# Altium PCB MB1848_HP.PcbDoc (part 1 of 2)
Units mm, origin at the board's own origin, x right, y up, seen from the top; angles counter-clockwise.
Board outline 61.5 x 34 mm, 4 copper layers (Top Layer, MidLayer 1, MidLayer 2, Bottom Layer), stack 1.035 mm thick; 124 components, 86 nets, 341 pads, 1082 vias.
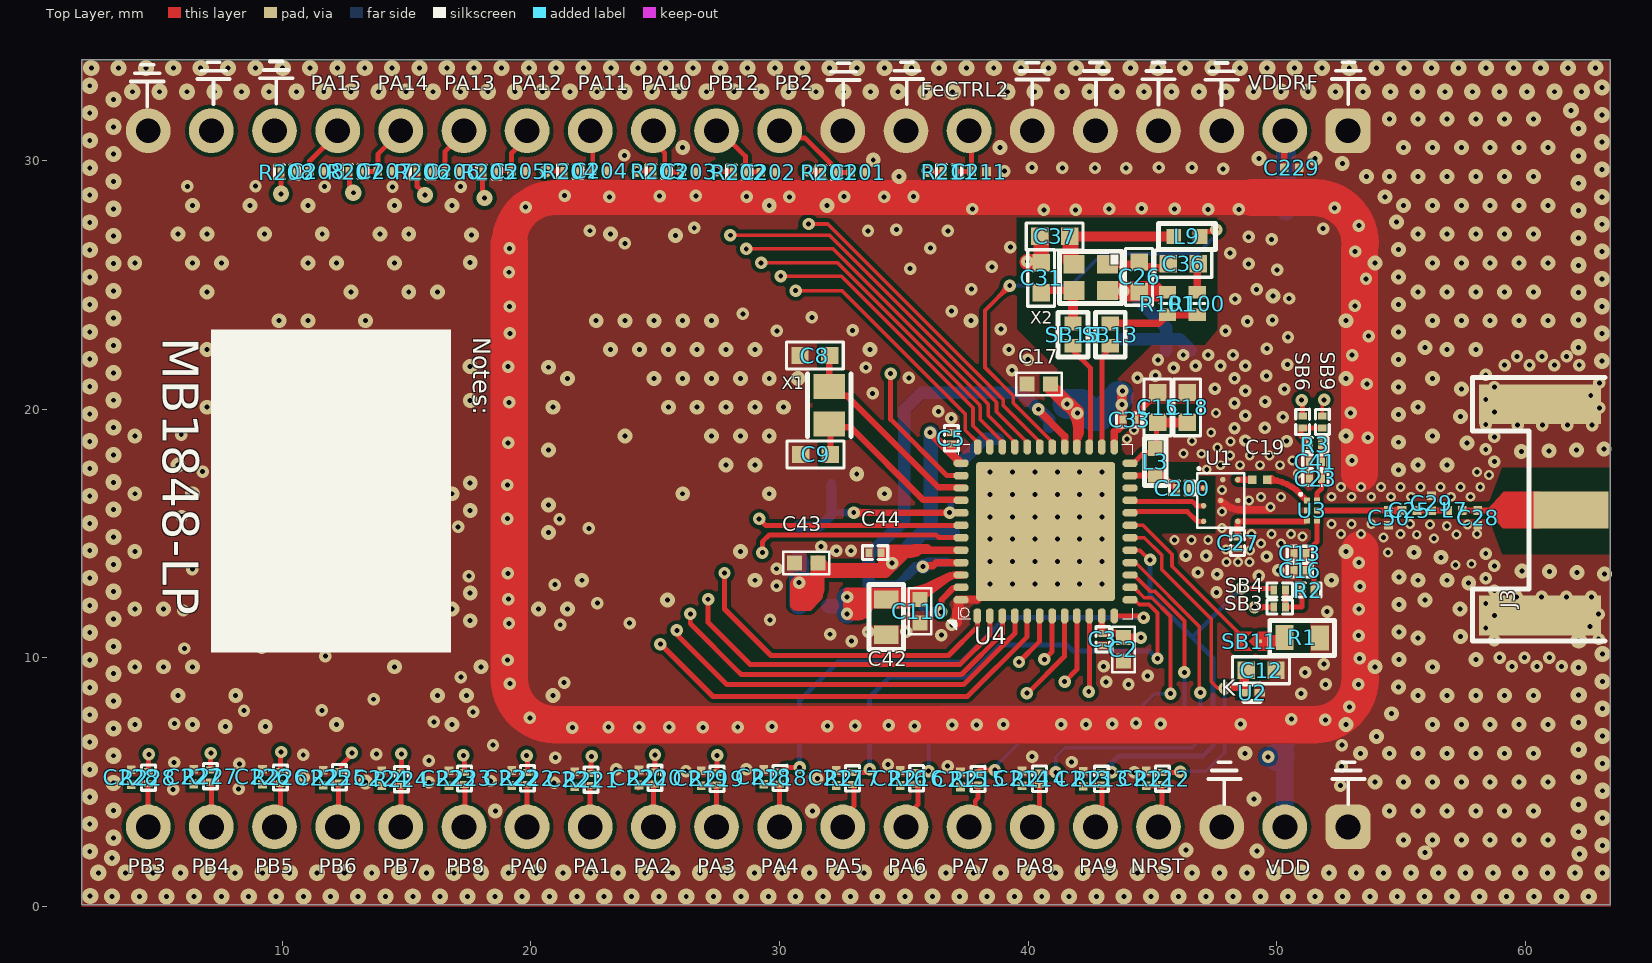
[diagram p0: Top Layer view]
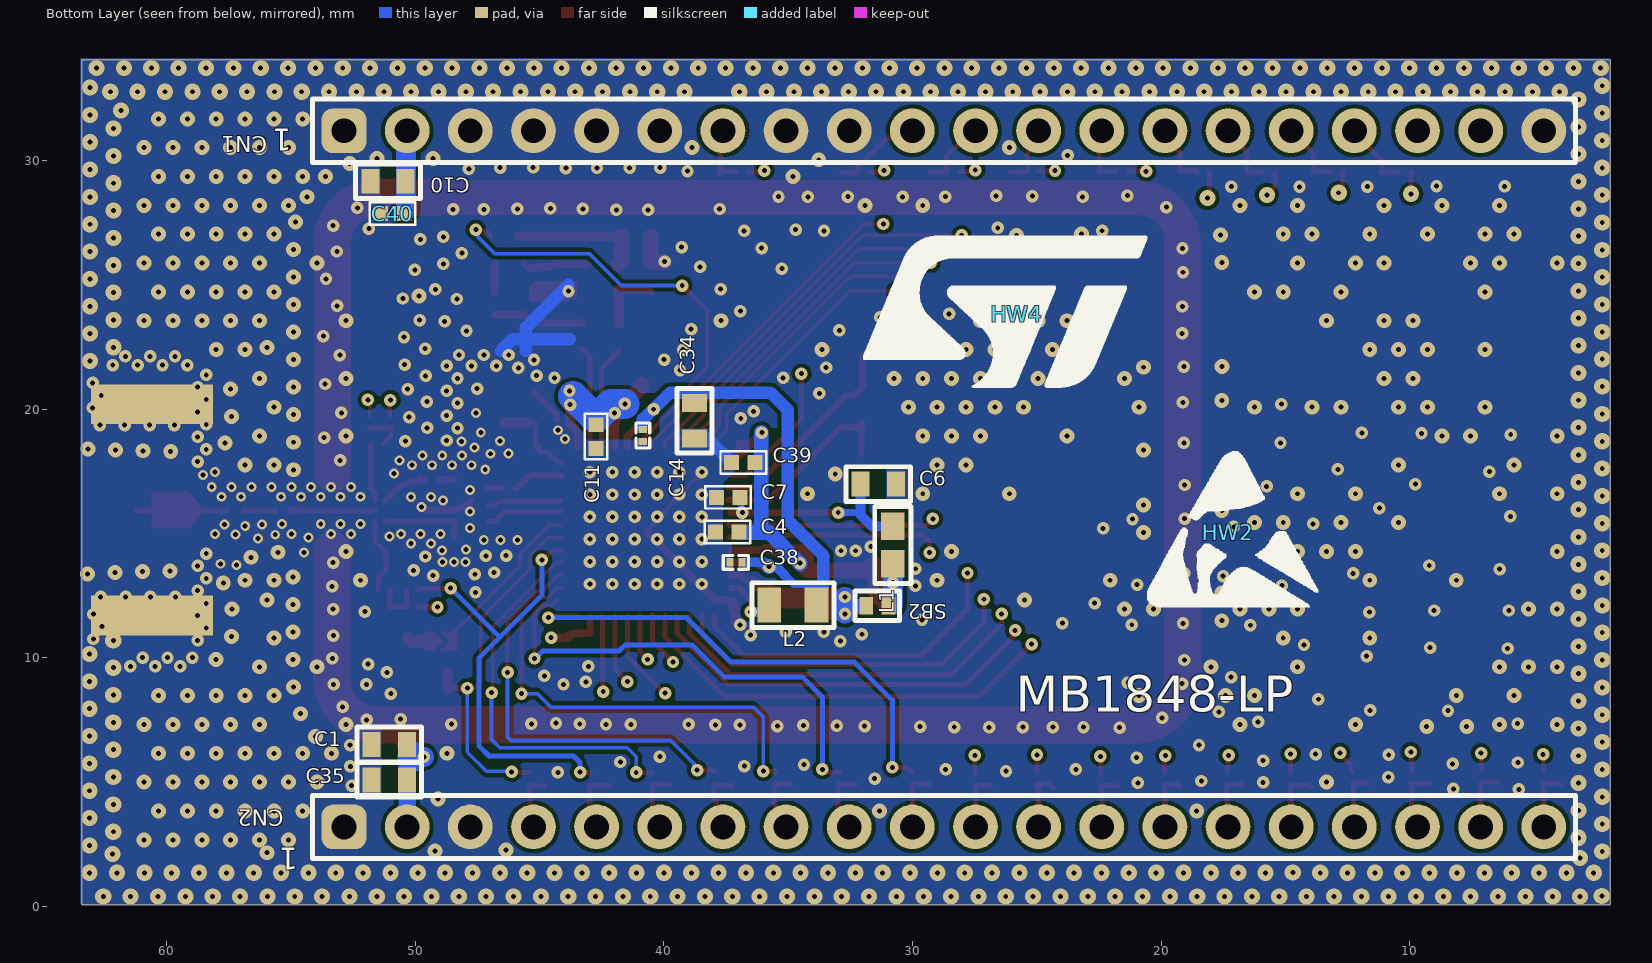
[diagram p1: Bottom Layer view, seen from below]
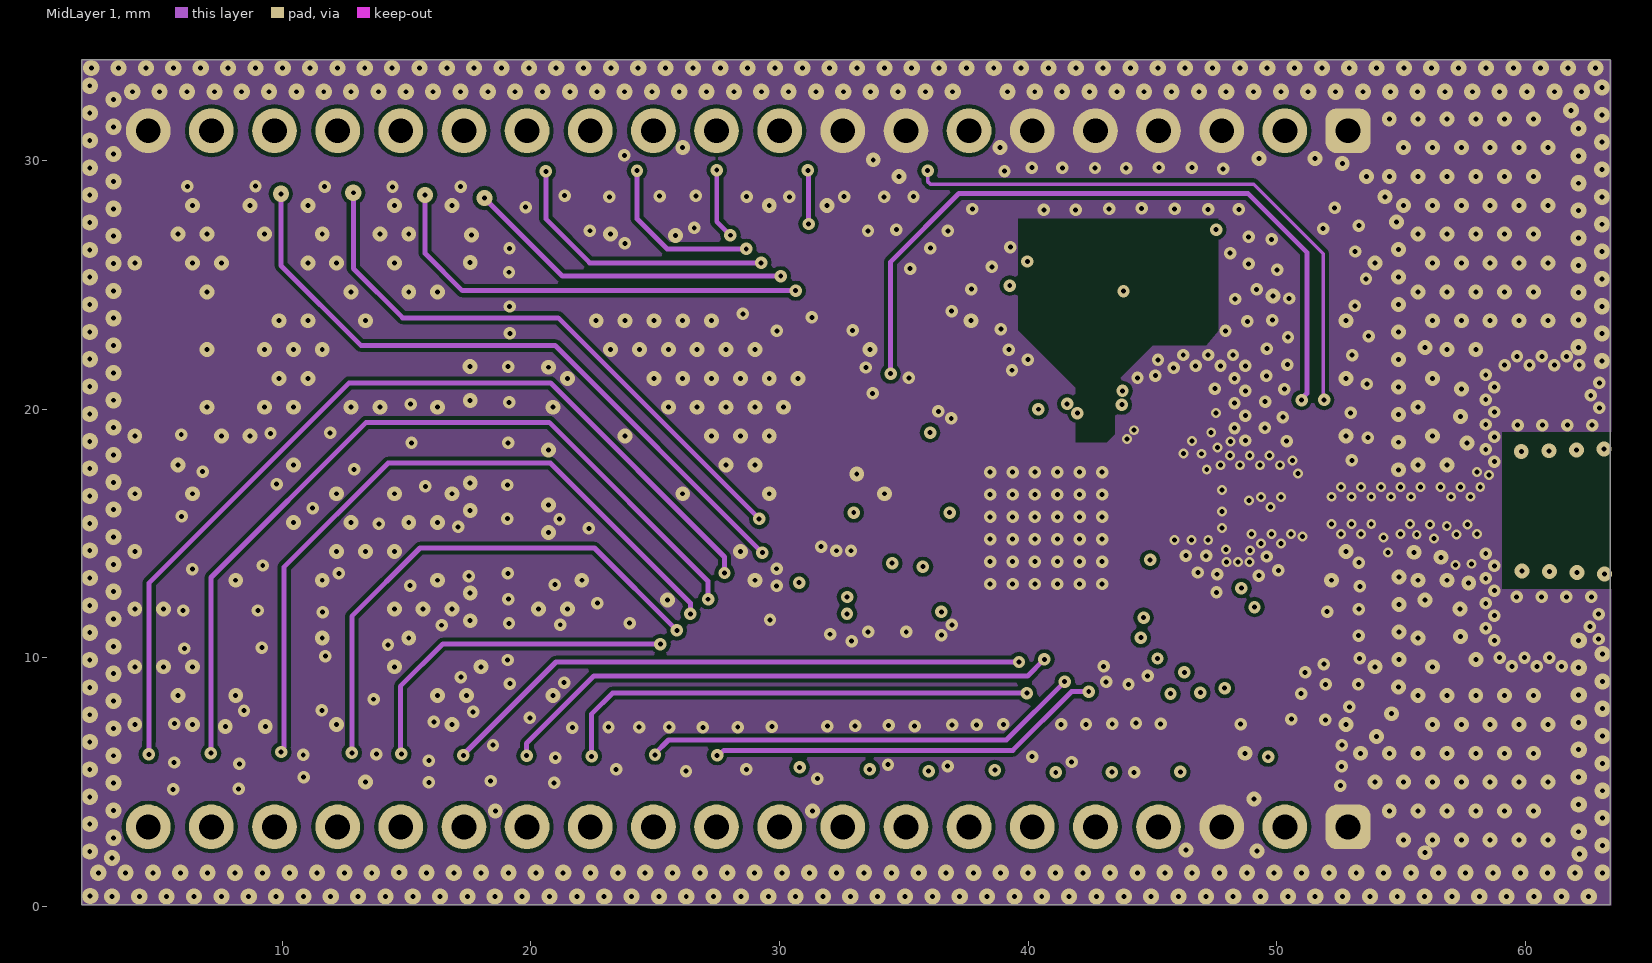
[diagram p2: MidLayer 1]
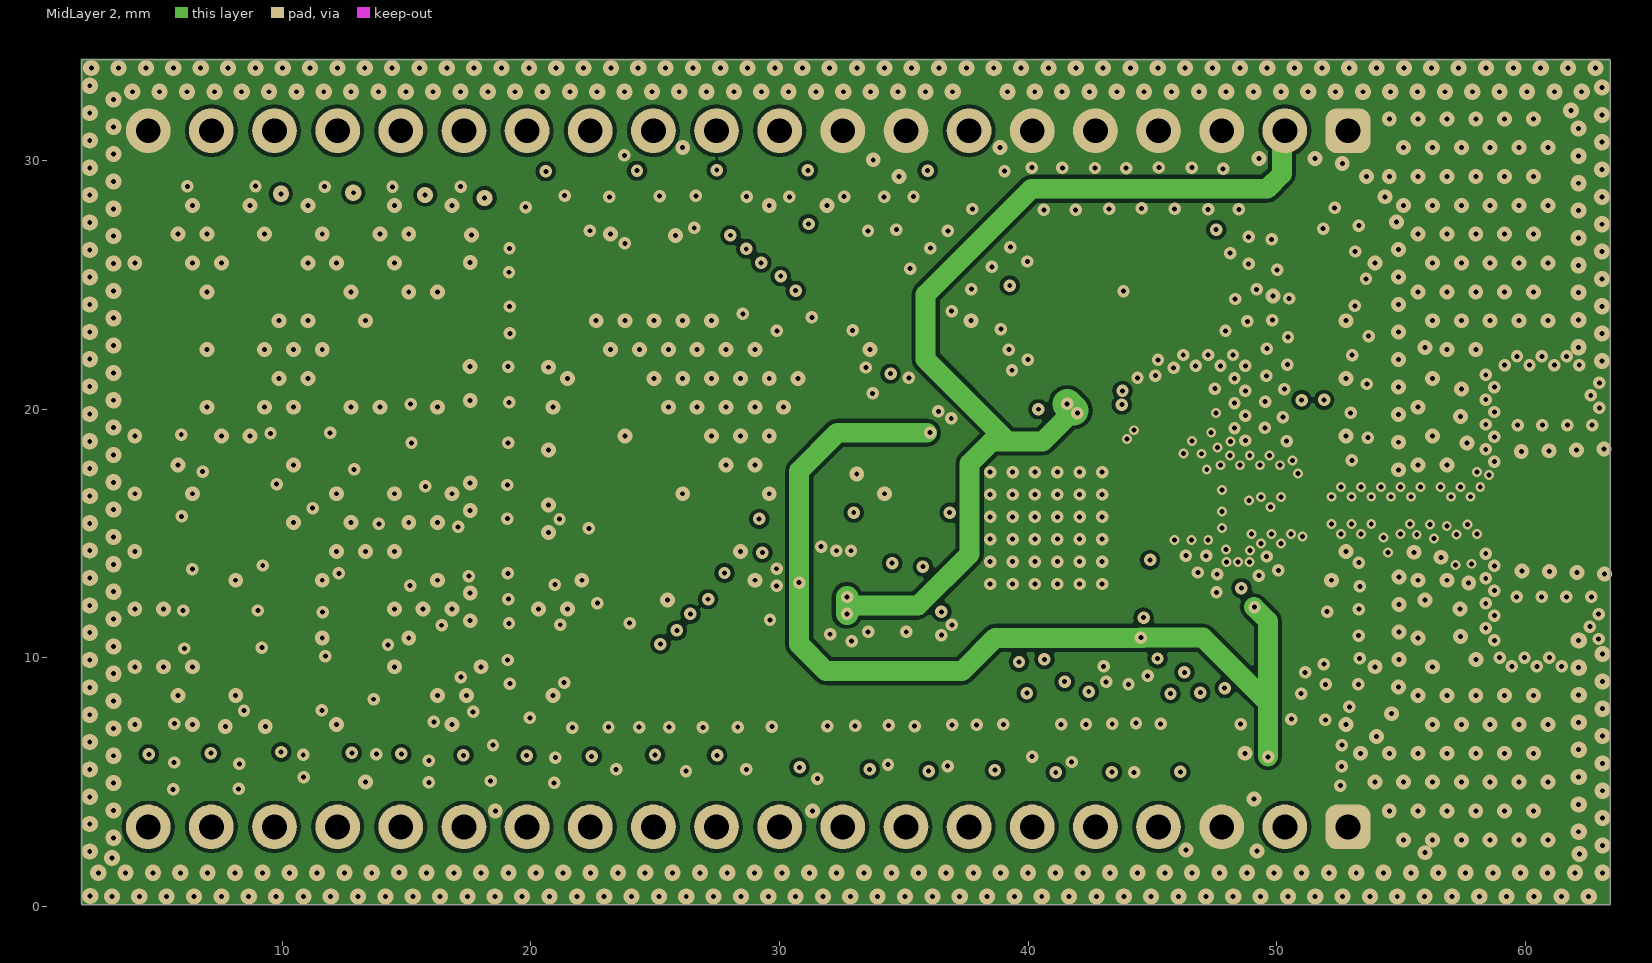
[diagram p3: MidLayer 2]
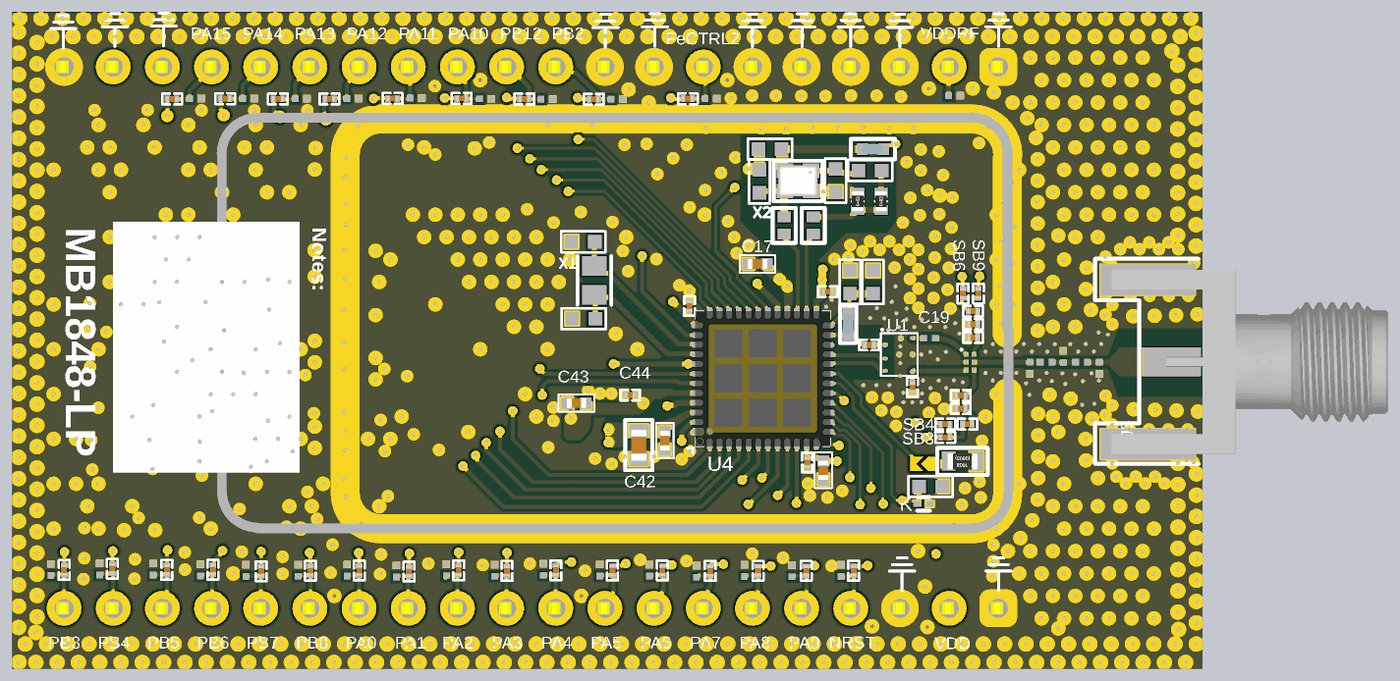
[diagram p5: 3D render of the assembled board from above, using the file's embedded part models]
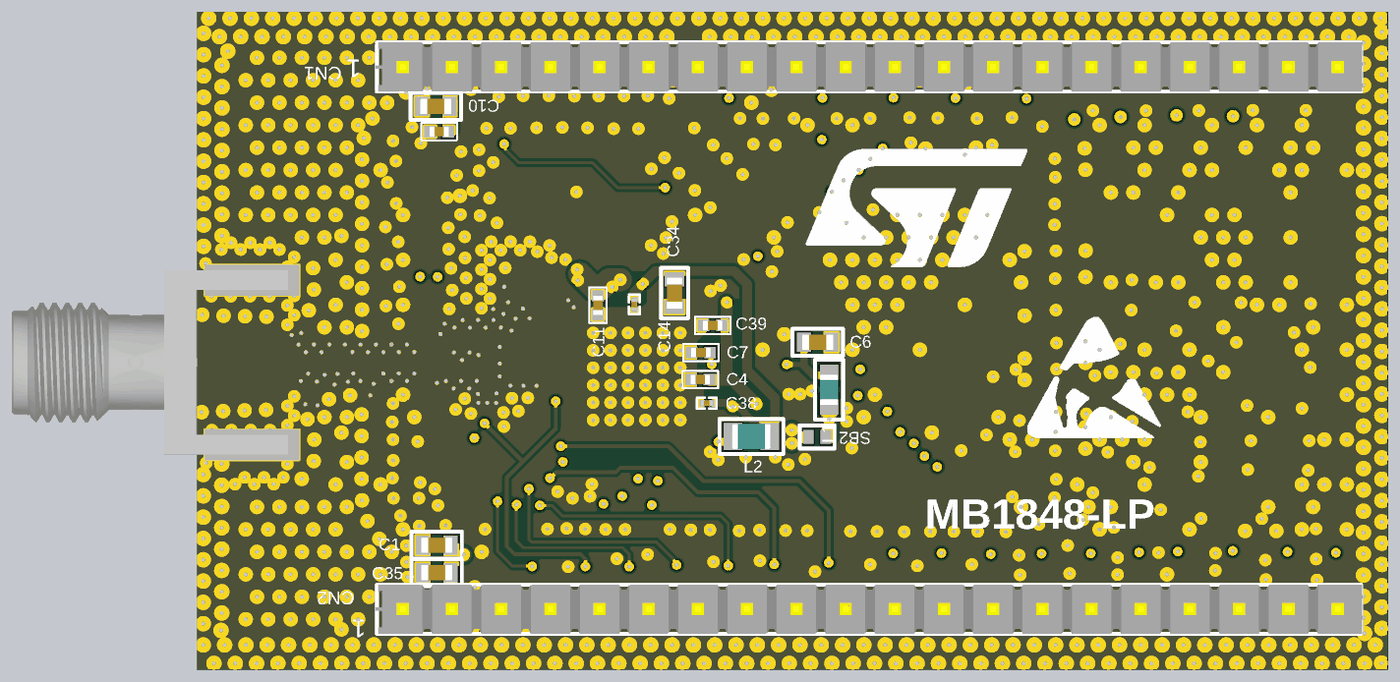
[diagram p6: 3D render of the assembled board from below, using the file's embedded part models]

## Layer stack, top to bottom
Top Solder: solder mask 0.01, Solder Resist, Dk 3.5
Top Layer: signal copper 0.035
Dielectric 2: prepreg 0.16, 1 x 2116 + 1 x 106, Dk 3.7
MidLayer 1: signal copper 0.0175
Dielectric 1: core 0.61, FR-4, Dk 5
MidLayer 2: signal copper 0.0175
Dielectric 3: prepreg 0.16, 1 x 2116 + 1 x 106, Dk 3.7
Bottom Layer: signal copper 0.035
Bottom Solder: solder mask 0.01, Solder Resist, Dk 3.5

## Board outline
1.922,0.056 63.42,0.056 63.42,34.056 1.942,34.056 1.922,34.056

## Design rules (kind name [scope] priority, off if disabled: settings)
BoardOutlineClearance [All] p1 off: gap=0.6 ignorepadtopadclearanceinfootprint=FALSE
Clearance Clearance_GND_50ohm [InNetClass('50ohm') or  (InDifferentialPairClass('All Differential Pairs')) vs InNamedPolygon('TOP_LAYER_GND')] p1: gap=0.175 ignorepadtopadclearanceinfootprint=FALSE except(0: Arc-Hole Track-Hole SMDPad-Hole THPad-Hole Via-Hole Fill-Hole Poly-Hole Region-Hole Text-Hole; 0.165: Arc-Fill Arc-Poly Arc-Region Track-Fill Track-Poly Track-Region)
Clearance Clearance_tab [(ObjectKind = 'Pad') And (Name Like 'Tab*-*') vs OnLayer('Keep-Out Layer')] p2: gap=0 ignorepadtopadclearanceinfootprint=FALSE
Clearance Clearance_via_to_via [(ObjectKind = 'Via') And (Net <> 'GND') vs (ObjectKind = 'Via') And (Net <> 'GND')] p3: gap=0.25 ignorepadtopadclearanceinfootprint=FALSE except(0: Arc-Hole Track-Hole SMDPad-Hole THPad-Hole Via-Hole Fill-Hole Poly-Hole Region-Hole Text-Hole)
Clearance [All] p4: gap=0.1 ignorepadtopadclearanceinfootprint=FALSE except(0: Arc-Hole Track-Hole SMDPad-Hole THPad-Hole Via-Hole Fill-Hole Poly-Hole Region-Hole Text-Hole; 0.15: Arc-Fill Arc-Poly Arc-Region Track-Fill Track-Poly Track-Region SMDPad-Fill SMDPad-Poly SMDPad-Region THPad-Fill THPad-Poly THPad-Region Via-Fill Via-Poly Via-Region Fill-Fill Fill-Poly Fill-Region Poly-Poly Poly-Region Region-Region)
ComponentClearance [All] p1: gap=0 collisioncheckmode=3 verticalgap=0.1 showdistances=FALSE
DiffPairsRouting [InDifferentialPair('RFI')] p1: maxlimit=0.3 minlimit=0.25 mostfreqgap=0.3 toplayer_minwidth=0.1 toplayer_maxwidth=0.24 toplayer_prefwidth=0.1 midlayer1_minwidth=0.145 midlayer1_maxwidth=0.24 midlayer1_prefwidth=0.145 midlayer2_minwidth=0.145 midlayer2_maxwidth=0.24 midlayer2_prefwidth=0.145 bottomlayer_minwidth=0.1 bottomlayer_maxwidth=0.24 bottomlayer_prefwidth=0.1 maxuncoupledlength=12.7
HoleSize [All] p1: absolutevalues=TRUE maxlimit=10 minlimit=0.025 maxpercent=80.000 minpercent=20.000
HoleToHoleClearance [All] p1: gap=0.25 allowstackedmicrovias=TRUE
MaximumViaCount MaximumViaCount_5 [InNet('GND')] p1: limit=1300
MaximumViaCount MaximumViaCount_4 [InNet('VDDRF1V55')] p2: limit=1000
MaximumViaCount MaximumViaCount_3 [InNet('VDDPA')] p3: limit=1000
MaximumViaCount MaximumViaCount_2 [InNet('VDDRF')] p4: limit=1000
MaximumViaCount MaximumViaCount_1 [InNet('VDD')] p5: limit=1000
MaximumViaCount [All] p6: limit=3
MinimumSolderMaskSliver [All] p1: minsoldermaskwidth=0.1
PlaneConnect [InNet('GND')] p1: planeconnectstyle=Relief reliefexpansion=0.508 reliefentries=4 reliefconductorwidth=0.21 reliefairgap=0.21
PolygonConnect PolygonConnect_J1 [(ObjectKind = 'Pad') And (Name = 'J1-2')] p1: connectstyle=Direct reliefconductorwidth=0.254 reliefentries=4 polygonreliefangle="90 Angle" airgapwidth=0.254
PolygonConnect PolygonConnect_All [All] p2: connectstyle=Direct reliefconductorwidth=0.25 reliefentries=4 polygonreliefangle="90 Angle" airgapwidth=0.25
RoutingLayers "RoutingLayers_90 Ohms" [InDifferentialPairClass('All Differential Pairs')] p1: top layer_v5=TRUE mid layer 1_v5=TRUE mid layer 2_v5=TRUE bottom layer_v5=TRUE
RoutingLayers [All] p2: top layer_v5=TRUE mid layer 1_v5=TRUE mid layer 2_v5=TRUE bottom layer_v5=TRUE
RoutingVias RoutingVias_BGA [InDrillLayerPair('Top Layer - MidLayer 1')] p1: holewidth=0.125 width=0.25 viastyle="Through Hole" minholewidth=0.125 minwidth=0.25 maxholewidth=0.125 maxwidth=0.3
RoutingVias [All] p2: holewidth=0.2 width=0.65 viastyle="Through Hole" minholewidth=0.2 minwidth=0.4 maxholewidth=0.2 maxwidth=0.7
ShortCircuit [(ObjectKind = 'Via') And (DrillPair = 'Top Layer - MidLayer 1') vs Ispad] p1: allowed=TRUE
SilkToSilkClearance [All] p1: silktosilkclearance=0.08
SilkToSolderMaskClearance [IsPad] p1: minsilkscreentomaskgap=0.08 clearancetoexposedcopper=TRUE
SolderMaskExpansion SolderMaskExpansion_VIA [IsVia] p1: expansion=-0.2 istentingtop=FALSE
SolderMaskExpansion [All] p2: expansion=0.075 istentingtop=FALSE
Width Width_50Ohms [InNetClass('50Ohms')] p1: maxlimit=0.7 minlimit=0.1 preferedwidth=0.24 midlayer1_maxwidth=0.5 midlayer2_maxwidth=0.5 bottomlayer_maxwidth=0.5 minimp=50.000000 maximp=50.000000 favimp=50.000000
Width [All] p2: maxlimit=2 minlimit=0.08 preferedwidth=0.15 toplayer_minwidth=0.097 toplayer_maxwidth=1.5 midlayer1_maxwidth=1 midlayer2_minwidth=0.1 bottomlayer_minwidth=0.1 bottomlayer_maxwidth=1.5 minimp=50.000000 maximp=50.000000 favimp=50.000000
20 further rules are at their usual default settings.

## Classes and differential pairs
component class Reference_Design_STM32WL_4L_IPD_ST: C1 C2 C3 C4 C5 C6 C7 C8 C9 C10 C11 C12 C13 C14 C15 C16 C17 C18 C19 C23 C25 C26 C27 C28 C29 C31 C33 C34 C35 C36 C37 C38 C39 C40 C41 C42 C43 C44 C110 CN1 CN2 J3 L1 L2 L3 L7 L9 R1 R2 R3 R100 R101 S1 SB2 SB3 SB4 SB6 SB9 SB11 SB13 SB15 U1 U2 U3 U4 X1 X2
net class 50ohm: NetC15_1 NetC19_1 NetC19_2 NetC25_1 NetC25_2 NetC27_2 NetC28_2
differential pair RFI: +RFI_P -RFI_N

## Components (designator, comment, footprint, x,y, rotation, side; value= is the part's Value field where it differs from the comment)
C1 "" CAPC1608X09N 51.049,6.501 r180 bottom
C2 "" CAPC1005X06N 43.826,10.333 r90 top
C3 "" 0201 43.003,10.492 r90 top
C4 "" CAPC1005X06N 37.443,15.048 r180 bottom
C5 "" 0201 36.91,19.063 r270 top
C6 "" CAPC1608X09N 31.375,16.977 r180 bottom
C7 "" CAPC1005X06N 37.41,16.448 r0 bottom
C8 "Capacitor" 0402 32.016,22.152 r180 top
C9 "Capacitor" 0402 32.043,18.172 r180 top
C10 "" CAPC1608X09N 51.093,29.164 r0 bottom
C11 "" CAPC1005X06N 42.723,18.892 r270 bottom
C12 "" 0402 48.768,9.492 r0 top
C13 "MCD-00198" 0201 50.687,14.2 r0 top
C14 "" CAPC1608X09N 38.769,19.522 r270 bottom
C15 "" 0402 45.203,19.467 r90 top
C16 "MCD-00102" 0201 50.687,13.515 r0 top
C17 "" CAPC1005X06N 40.427,21.003 r180 top
C18 "" 0402 46.393,20.663 r270 top
C19 "RFCapacitor_201" rlc_201_smd 49.311,17.158 r180 top
C23 "MCD-00198" 0201 51.312,17.196 r0 top
C25 "RFCapacitor_201" rlc_201_smd 55.336,15.919 r0 top
C26 "Capacitor" 0402 44.458,25.913 r270 top
C27 "NC" 0201 48.428,14.381 r90 top
C28 "RFCapacitor_201" rlc_201_smd 58.084,15.619 r90 top
C29 "RFCapacitor_201" rlc_201_smd 56.22,16.209 r270 top
C31 "Capacitor" 0402 40.521,24.68 r90 top
C33 "" 0201 44.296,19.562 r180 top
C34 "" 0201 40.843,18.693 r90 bottom
C35 "" CAPC1608X09N 51.049,5.083 r180 bottom
C36 "" 0402 46.836,25.842 r180 top
C37 "" 0402 40.468,26.942 r0 top
C38 "" 0201 36.863,13.832 r0 bottom
C39 "" CAPC1005X06N 36.802,17.848 r0 bottom
C40 "" CAPC1005X06N 50.916,27.859 r0 bottom
C41 "MCD-00102" 0201 51.792,17.882 r180 top
C42 "" CAPC1608X09N 34.292,11.632 r270 top
C43 "" CAPC1005X06N 31.071,13.802 r0 top
C44 "" 0201 33.6,14.223 r0 top
C50 "RFCapacitor_201" rlc_201_smd 54.496,15.626 r90 top value=NC
C110 "" CAPC1005X06N 35.642,11.864 r270 top
C200 "MCD-00198" 0201 46.436,16.815 r180 top
C201 "RFCapacitor_201" rlc_201_smd 33.163,29.521 r0 top value=NC
C202 "RFCapacitor_201" rlc_201_smd 29.546,29.525 r0 top value=NC
C203 "RFCapacitor_201" rlc_201_smd 26.365,29.542 r0 top value=NC
C204 "RFCapacitor_201" rlc_201_smd 22.785,29.577 r0 top value=NC
C205 "RFCapacitor_201" rlc_201_smd 19.515,29.563 r0 top value=NC
C206 "RFCapacitor_201" rlc_201_smd 16.847,29.55 r0 top value=NC
C207 "RFCapacitor_201" rlc_201_smd 14.138,29.558 r0 top value=NC
C208 "RFCapacitor_201" rlc_201_smd 11.393,29.558 r0 top value=NC
C211 "RFCapacitor_201" rlc_201_smd 38.022,29.553 r180 top value=NC
C212 "RFCapacitor_201" rlc_201_smd 44.745,5.141 r90 top value=NC
C213 "RFCapacitor_201" rlc_201_smd 42.208,5.125 r90 top value=NC
C214 "RFCapacitor_201" rlc_201_smd 39.752,5.141 r90 top value=NC
C215 "RFCapacitor_201" rlc_201_smd 37.279,5.1 r90 top value=NC
C216 "RFCapacitor_201" rlc_201_smd 34.85,5.156 r90 top value=NC
C217 "RFCapacitor_201" rlc_201_smd 32.274,5.158 r90 top value=NC
C218 "RFCapacitor_201" rlc_201_smd 29.366,5.201 r90 top value=NC
C219 "RFCapacitor_201" rlc_201_smd 26.848,5.149 r90 top value=NC
C220 "RFCapacitor_201" rlc_201_smd 24.348,5.178 r90 top value=NC
C221 "RFCapacitor_201" rlc_201_smd 21.766,5.107 r90 top value=NC
C222 "RFCapacitor_201" rlc_201_smd 19.224,5.158 r90 top value=NC
C223 "RFCapacitor_201" rlc_201_smd 16.7,5.148 r90 top value=NC
C224 "RFCapacitor_201" rlc_201_smd 13.994,5.147 r90 top value=NC
C225 "RFCapacitor_201" rlc_201_smd 11.646,5.165 r90 top value=NC
C226 "RFCapacitor_201" rlc_201_smd 9.202,5.208 r90 top value=NC
C227 "RFCapacitor_201" rlc_201_smd 6.438,5.214 r90 top value=NC
C228 "RFCapacitor_201" rlc_201_smd 3.919,5.187 r90 top value=NC
C229 "RFCapacitor_201" rlc_201_smd 50.599,29.71 r0 top value=NC
CN1 "CON20" CO_SAMTEC_TSW-120-07-X-S 28.733,31.192 r180 bottom
CN2 "CON20" CO_SAMTEC_TSW-120-07-X-S 28.733,3.192 r180 bottom
Designator16 "Comment" IMPEDANCE_TABLE 101.003,-30.826 r0 top
HW2 "Logo" LOGO_MAIN 17.315,15.048 r180 bottom
HW4 "Logo" LOGO_ST 25.803,23.812 r180 bottom
J3 "SMA" SMA_AMPHENOL_50ohms_Edge_PCB 63.334,15.939 r90 top
L1 "" INDC1608X95N 30.789,14.529 r90 bottom
L2 "" INDC2012X13N 34.803,12.112 r0 bottom
L3 "MCD-01330" IND_MURATA_LQW15A 45.11,17.878 r270 top
L7 "Ferrite" rlc_201_smd 57.162,15.919 r0 top
L9 "ferrite" IND_MURATA_LQW15A 46.383,26.942 r0 top
R1 "" RESC1608X05N 51.016,10.792 r180 top
R2 "MCD-00119" 0201 51.502,12.72 r180 top
R3 "MCD-00119" 0201 51.792,18.566 r180 top
R100 "Resistor" R0402 46.803,24.242 r90 top
R101 "Resistor" R0402 45.603,24.242 r90 top
R201 "MCD-00119" 0201 31.728,29.521 r0 top value=0
R202 "MCD-00119" 0201 28.14,29.533 r0 top value=0
R203 "MCD-00119" 0201 24.9,29.559 r0 top value=0
R204 "MCD-00119" 0201 21.334,29.563 r0 top value=0
R205 "MCD-00119" 0201 18.072,29.537 r0 top value=0
R206 "MCD-00119" 0201 15.41,29.539 r0 top value=0
R207 "MCD-00119" 0201 12.683,29.55 r0 top value=0
R208 "MCD-00119" 0201 9.946,29.532 r0 top value=0
R211 "MCD-00119" 0201 36.58,29.553 r0 top value=100R
R212 "MCD-00119" 0201 45.394,5.371 r270 top value=0
R213 "MCD-00119" 0201 42.939,5.366 r270 top value=0
R214 "MCD-00119" 0201 40.452,5.369 r270 top value=0
R215 "MCD-00119" 0201 37.985,5.36 r270 top value=0
R216 "MCD-00119" 0201 35.512,5.388 r270 top value=0
R217 "MCD-00119" 0201 32.934,5.386 r270 top value=0
R218 "MCD-00119" 0201 30.012,5.4 r270 top value=0
R219 "MCD-00119" 0201 27.481,5.363 r270 top value=0
R220 "MCD-00119" 0201 24.981,5.401 r270 top value=0
R221 "MCD-00119" 0201 22.423,5.332 r270 top value=0
R222 "MCD-00119" 0201 19.851,5.387 r270 top value=0
R223 "MCD-00119" 0201 17.324,5.379 r270 top value=0
R224 "MCD-00119" 0201 14.785,5.353 r270 top value=0
R225 "MCD-00119" 0201 12.293,5.43 r270 top value=0
R226 "MCD-00119" 0201 9.915,5.419 r270 top value=0
R227 "MCD-00119" 0201 7.101,5.476 r270 top value=0
R228 "MCD-00119" 0201 4.612,5.415 r270 top value=0
SB2 "Open" SB_0402 31.413,12.088 r0 bottom
SB3 "Close" 0201 49.877,12.034 r0 top
SB4 "Open" 0201 49.877,12.718 r0 top
SB6 "Close" 0201 51.041,19.72 r270 top
SB9 "Open" 0201 51.832,19.72 r270 top
SB11 "Close" GC_0402 48.953,10.661 r180 top
SB13 "Close" SB_0402 43.303,22.992 r90 top
SB15 "Close" SB_0402 41.803,22.992 r90 top
U1 "IPD STM STM32WL" "IPD STM" 47.744,16.319 r180 top
U2 "" DIOM0603X03N 49.003,8.592 r0 top
U3 "BGS12SN6" TSNP-6-2 51.411,15.919 r0 top
U4 "STM32WLxx_QFN48" STM32WLXX_QFN48 40.701,15.075 r90 top
X1 "XTAL_2_PINS" OSC_NDK_NX2012SA 31.998,20.154 r90 top
X2 "" OSC_NDK_NX2016SA 42.513,25.295 r180 top

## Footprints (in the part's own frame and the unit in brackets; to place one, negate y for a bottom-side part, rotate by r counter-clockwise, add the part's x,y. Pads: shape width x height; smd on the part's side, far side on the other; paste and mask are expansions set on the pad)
0201 [mm]
  rect 0.28x0.35 smd: 1(0,0) 2(0.48,0)
  silkscreen extent -0.27,-0.28 0.75,0.28, body extent -0.06,-0.15 0.54,0.15, height 0.3
0402 [mm] "Chip Capacitor, Body 1.0x0.5mm, IPC High Density"
  rect 0.7x0.7 smd: 1(-0.001,0) 2(1.197,0)
  silkscreen extent -0.54,-0.54 1.74,0.54, body extent -0.42,-0.36 1.62,0.36, height 0.82
CAPC1005X06N [mm] "Chip Capacitor, 2-Leads, Body 1.00x0.70x0.70mm (0402)"
  rect 0.6x0.6 smd: 1(-0.475,0) 2(0.475,0)
  silkscreen extent -0.92,-0.45 0.92,0.45, body extent -0.5,-0.25 0.5,0.25, height 0.6
CAPC1608X09N [mm] "Chip Capacitor, 2-Leads, Body 1.60x0.80x0.90mm (0603)"
  rect 0.725x1 smd: 1(-0.713,0) 2(0.713,0)
  Top Layer pour cut-out: -0.3,0.7 0.3,0.7 0.3,-0.7 -0.3,-0.7
  silkscreen extent -1.3,-0.7 1.3,0.7, body extent -0.8,-0.4 0.8,0.4, height 0.9
CO_SAMTEC_TSW-120-07-X-S [mm] "Header, 20-Leads, 50.80x2.54x10.80mm, Pitch 2.54mm"
  rrect50% 1.8x1.8 hole 1: 1(-24.13,0)
  round 1.8 hole 1: 2(-21.59,0) 3(-19.05,0) 4(-16.51,0) 5(-13.97,0) 6(-11.43,0) 7(-8.89,0) 8(-6.35,0) 9(-3.81,0) 10(-1.27,0) 11(1.27,0) 12(3.81,0) 13(6.35,0) 14(8.89,0) 15(11.43,0) 16(13.97,0) 17(16.51,0) 18(19.05,0) 19(21.59,0) 20(24.13,0)
  silkscreen extent -25.4,-1.27 25.4,1.27, body extent -25.46,-1.27 25.46,1.27, height 8.38
DIOM0603X03N [mm] "Molded Diode, 2-Leads, Body 0.60x0.30mm"
  rect 0.425x0.3 smd: 1(-0.312,0) 2(0.313,0)
  silkscreen extent -0.32,-0.35 0.33,0.35, body extent -0.32,-0.18 0.33,0.18, height 0.33
GC_0402 [mm] "Grain de café format 0402"
  rect 0.15x0.15 smd paste-1: 1(-0.375,0) 2(0.45,0)
  Top Layer region: -0.65,0.375 -0.3,0.375 0.075,0 -0.3,-0.375 -0.65,-0.375
  Top Layer region: -0.05,0.375 0.65,0.375 0.65,-0.375 -0.05,-0.375 0.325,0
  body extent -0.5,-0.25 0.6,0.25, height 0.2
IMPEDANCE_TABLE [mm]
IND_MURATA_LQW15A [mm] "Inductor 2-Leads,Body 1.10x0.70x0.60mm(max)"
  rect 0.6x0.6 smd: 1(-0.53,0) 2(0.53,0)
  silkscreen extent -0.96,-0.42 0.96,0.42, body extent -0.5,-0.3 0.5,0.3, height 0.51
INDC1608X95N [mm] "Chip Inductor, 2-Leads, Body 1.75x0.95x0.95mm (0603)"
  rect 1.1x0.95 smd: 1(-0.75,0) 2(0.75,0)
  silkscreen extent -1.55,-0.72 1.55,0.72, body extent -0.8,-0.48 0.8,0.47, height 0.8
INDC2012X13N [mm] "Chip Inductor, 2-Leads, Body 2.0x1.2x1.3 (0805)"
  rect 0.96x1.4 smd: 1(-0.952,0) 2(0.952,0)
  silkscreen extent -1.65,-0.9 1.65,0.9, body extent -1,-0.65 1,0.65, height 1.18
"IPD STM" [mm] "IPD STM STM32WL, Body 2.20 x 1.90 x 0.710 mm (LxWxH max)"
  round 0.22 smd mask+0.05: 1(0.69,-0.5) 2(0.69,0.84) 3(0.69,0.21) 4(-0.69,0.84) 5(-0.69,0) 6(-0.69,-0.84) 7(-0.085,-0.84) 8(0,0)
  silkscreen extent -0.95,-1.33 0.95,1.1, body extent -0.84,-1 0.84,1, height 0.71
LOGO_MAIN [mm]
  silkscreen extent -3.24,-3.02 3.65,3.22
LOGO_ST [mm]
  silkscreen extent -6.18,-2.95 5.25,3.14
OSC_NDK_NX2012SA [mm] "Crystal, 2-Leads, Body 2.05x1.20x0.55mm (Tol:-/+0.05)"
  rect 1x1.25 smd: 1(-0.75,0) 2(0.75,0)
  silkscreen extent -1.25,-0.87 1.25,0.87, body extent -1.04,-0.63 1.03,0.63, height 0.55
OSC_NDK_NX2016SA [mm] "Crystal, 4-Leads, Body 2.10x1.61x0.50mm (max), Pitch 1.35x1.05mm"
  rect 0.85x0.75 smd: 1(-0.675,-0.525) 2(0.675,-0.525) 3(0.675,0.525) 4(-0.675,0.525)
  silkscreen extent -1.25,-1.05 1.25,1.05, body extent -1,-0.8 1,0.8, height 0.5
R0402 [mm]
  rect 0.51x0.7 smd mask+0.05: 1(-0.45,0) 2(0.45,0)
  silkscreen extent 0,-0.3 0,0.3, body extent -0.52,-0.3 0.52,0.3, height 0.4
RESC1608X05N [mm] "Chip Resistor, 2-Leads, Body 1.60x0.80mm (0603)"
  rect 0.725x1 smd: 1(-0.713,0) 2(0.712,-0.016)
  Top Layer pour cut-out: -0.3,0.7 0.3,0.7 0.3,-0.7 -0.3,-0.7
  silkscreen extent -1.3,-0.7 1.3,0.7, body extent -0.77,-0.42 0.78,0.43, height 0.45
rlc_201_smd [mm]
  rect 0.35x0.35 smd paste+0 mask+0.025: 1(-0.3,0) 2(0.3,0)
  body extent -0.3,-0.15 0.3,0.15, height 0.5
SB_0402 [mm] "Solder Bridge 0 Ohm (0402)"
  rect 0.55x0.7 smd: 1(-0.45,0) 2(0.45,0)
  silkscreen extent -0.9,-0.6 0.9,0.6, body extent -0.5,-0.25 0.5,0.25, height 0.25
SMA_AMPHENOL_50ohms_Edge_PCB [mm] "RF Connector, SMA End Launch Jack for 0.047 inch (1.19 mm thickness) PCB, 50 Ohm, Flat Tab Contact"
  rect 1.5x3 smd mask+0.05: 1(0,1.5)
  rect 1.6x4.9 smd mask+0.05: 2(-4.25,2.75) 2(4.25,2.75)
  rect 1.6x4.9 smd far side mask+0.05: 2(-4.25,2.75) 2(4.25,2.75)
  silkscreen extent -5.27,0.13 5.33,5.47, body extent -4.76,-9.65 4.76,4.62, height 4.09
STM32WLXX_QFN48 [mm] "QFN48 7x7x0.55mm pitch 0.5mm"
  oct 0.6x0.3 smd mask+0.06: 1(-3.398,2.746) 2(-3.398,2.239) 3(-3.398,1.739) 4(-3.398,1.239) 5(-3.398,0.739) 6(-3.398,0.239) 7(-3.398,-0.261) 8(-3.398,-0.761) 9(-3.398,-1.261) 10(-3.398,-1.761) 11(-3.398,-2.261) 12(-3.398,-2.761) 25(3.398,-2.761) 26(3.398,-2.261) 27(3.398,-1.761) 28(3.398,-1.261) 29(3.398,-0.761) 30(3.398,-0.261) 31(3.398,0.239) 32(3.398,0.739) 33(3.398,1.239) 34(3.398,1.739) 35(3.398,2.239) 36(3.398,2.739)
  oct 0.3x0.6 smd mask+0.06: 13(-2.752,-3.399) 14(-2.252,-3.399) 15(-1.752,-3.399) 16(-1.252,-3.399) 17(-0.752,-3.399) 18(-0.252,-3.399) 19(0.248,-3.399) 20(0.748,-3.399) 21(1.248,-3.399) 22(1.748,-3.399) 23(2.248,-3.399) 24(2.748,-3.399) 37(2.748,3.399) 38(2.248,3.399) 39(1.748,3.399) 40(1.248,3.399) 41(0.748,3.399) 42(0.248,3.399) 43(-0.252,3.399) 44(-0.752,3.399) 45(-1.252,3.399) 46(-1.752,3.399) 47(-2.252,3.399) 48(-2.752,3.399)
  rrect5% 5.6x5.6 smd paste-3 mask+0.08: 49(0,0)
  silkscreen extent -3.95,-3.5 3.5,3.96, body extent -3.51,-3.51 3.51,3.51, height 0.78
TSNP-6-2 [mm] "TSNP-6-2; Body 1.1 x 0.7 mm (LxW typ)"
  rect 0.25x0.25 smd paste-0.025 mask+0.025: 1(-0.2,0.4) 2(-0.2,0) 3(-0.2,-0.4) 4(0.2,-0.4) 5(0.2,0) 6(0.2,0.4)
  silkscreen extent -0.5,0.6 -0.4,0.7, body extent -0.35,-0.55 0.35,0.55, height 0.45

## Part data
C1 C6 C10 C35 C42: library part MCD-00009, "Capacitor, MLCC, 4.7uF, 16V, X5R, 10%, 0603, T=0.8mm"
C2 C4 C7 C11 C12 C17 C39 C40 C43 C110: library part MCD-00102, "Capacitor, MLCC, 100nF, 16V, X7R, 10%, 0402, T=0,5mm"
C3 C5 C44: library part MCD-00102, "Multilayer Ceramic Capacitors MLCC - SMD/SMT 0201 25VDC 0.1uF 10% X5R 0.3mm"
C8 C9: library part MCD-00003, "Capacitor, MLCC, 6.8pF, 50V, NPO, +-0.1pF, 0402, T=0.5mm"
C13 C23: "Multilayer ceramic capacitors X7R ±10%, 50V"
C14: library part MCD-00009, "Capacitor, MLCC, 4.7 uF, 16V, X5R, 10%, 0603, T=0.8mm"
C15: library part MCD-01123, "Capacitor, MLCC,47nF, 16V, X7R, 10%, 0402, T=0.5mm"
C16 C41: "Multilayer ceramic capacitors X5R ±10%, 10V"
C18: library part MCD-01123, "Capacitor, MLCC,68pF, 50V, C0G, 1%, 0402, T=0.5mm"
C19 C25: "Multilayer ceramic capacitors COG ±5%, 50V"
C26 C31: library part MCD-00003, "Not connected"
C27: library part RFCapacitor_201, "RF Capacitor High-Q, 0201"
C28 C29 C50 C201 C202 C203 C204 C205 C206 C207 C208 C211 C212 C213 C214 C215 C216 C217 C218 C219 C220 C221 C222 C223 C224 C225 C226 C227 C228 C229: "RF Capacitor High-Q, 0201"
C33 C34: library part MCD-00277, "Multilayer Ceramic Capacitors MLCC - SMD/SMT 0201 33pF 25volts C0G 5%"
C36 C37: library part MCD-00277, "Capacitor, MLCC, 33pF, 50V, NPO, 2%, 0402, T=0,5mm"
C38: library part MCD-01123, "Multilayer Ceramic Capacitors MLCC - SMD/SMT 0201 33pF 25volts C0G 5%"
C200: "Multilayer ceramic capacitors COG +/-5%, 50V"
CN1 CN2: "Connector right-angle, pitch 2.54mm, 20 contacts"
Designator16: library part MCD-00279
HW2: library part MCD-00627, "\"Hand\" ESD logo footprint for PCB"
HW4: library part MCD-00625, "\"STMicroelectronics\" logo footprint for PCB"
J3: "SMA Straight Connector"
L1: library part MCD-00047, "SMD Chip ferrite bead, 600R@100MHz +/-25%, 350mA, 500mohm DC, 0603, T=0.8mm"
L2: library part MCD-01433, "MLZ2012 Multilayer Shielded Inductor 15 uH, ±5%"
L3: "Inductor, 47nH, +-0.1nH, 140mA, 0402"
L7: library part RFInductor_201, "Thick Film Resistor ±5%, 1/20W"
L9: library part MCD-01330, "Not connected"
R1: library part MCD-00220, "Resistor,10K,0603,1%,1/10W"
R2 R3: "Thick Film Resistors - SMD 1/20watt 100ohms 5% 200ppm"
R100: library part MCD-00052, "Resistor,0R,0402,5%,1/16W"
R101: library part MCD-00052, "Not connected"
R201 R202 R203 R204 R205 R206 R207 R208 R211 R212 R213 R214 R215 R216 R217 R218 R219 R220 R221 R222 R223 R224 R225 R226 R227 R228: "Thick Film Resistors - SMD 1/20watt 100ohms 5% 200ppm", Manufacturer="Vishay / Dale", Manufacturer_Part_Number=CRCW0201100RJNED
SB2 SB4 SB9: library part SB_Open, "Solder Bridge Open [0402] (Unpopulated)"
SB3 SB6: library part SB_0Ohm, "Thick Film Resistors - SMD 1/20watt ZEROohm Jumper"
SB11: library part Strap2, "Solder Jumper - Close"
SB13 SB15: library part SB_0Ohm, "Solder Bridge 0R [0402] (Populated with 0 Ohm)"
U1: library part "IPD ST STM32WL"
U2: library part MCD-00170, "ESD protection 6V1"
U3: "DC switch - Ultra-Low  SPDT analog switch"
U4: "STM32WL ARM MCU Multiprotocol LPWAN 32-bit Arm Cortex-M4 MCUs LoRa (G)FSK-MSK BPSK"
X1: library part MCD-01479, "Crystal 32.768kHz, 6pF, -+20PPM, R=80K, SMD"
X2: library part MCD-01446, "Crystal 32 MHz, 8pF, -+10 PPM, R=60Ω, SMD"

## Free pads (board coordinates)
  round 0.508 on Mech16: 1(72.036,-25.742)

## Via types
v1: diameter 0.5, hole 0.2, Top Layer to Bottom Layer, 395 vias
v2: diameter 0.65, hole 0.2, Top Layer to Bottom Layer, 321 vias
v3: diameter 0.6, hole 0.2, Top Layer to Bottom Layer, 291 vias
v4: diameter 0.4, hole 0.2, Top Layer to Bottom Layer, tented both sides, 75 vias

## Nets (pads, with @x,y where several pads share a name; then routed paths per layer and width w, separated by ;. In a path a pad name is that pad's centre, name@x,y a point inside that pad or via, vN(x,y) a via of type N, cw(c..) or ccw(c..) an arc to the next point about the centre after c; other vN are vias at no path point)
GND: C1.1 C2.1 C3.1 C4.1 C5.1 C6.2 C7.2 C8.2 C9.2 C10.2 C11.2 C12.2 C13.1 C14.2 C15.2 C16.1 C17.2 C18.1 C23.1 C26.2 C27.1 C28.1 C29.1 C31.2 C33.1 C34.1 C35.1 C37.1 C38.2 C39.2 C40.2 C41.2 C42.2 C43.1 C44.1 C50.1 C110.2 C201.2 C202.2 C203.2 C204.2 C205.2 C206.2 C207.2 C208.2 C211.1 C212.2 C213.2 C214.2 C215.2 C216.2 C217.2 C218.2 C219.2 C220.2 C221.2 C222.2 C223.2 C224.2 C225.2 C226.2 C227.2 C228.2 C229.2 CN1.1 CN1.3 CN1.4 CN1.5 CN1.6 CN1.8 CN1.9 CN1.20 CN2.1 CN2.3 J3.2 R1.1 R101.2 U1.5 U1.7 U1.8 U2.2 U3.2 U4.48 U4.49 X2.4 | length 127.4
  Top Layer w0.15: v1@6.007,10.418 v1(6.059,10.366) ; v1(8.456,7.866) v1@8.47,7.881 ; v1(38.471,17.462) 39.339,16.532 40.208,15.603 U4.49@40.701,15.075 ; v1(48.815,23.523) v1@48.815,23.557 ; v1(50.014,25.598) v1@50.014,25.637
  Top Layer w0.2: U4.48@37.302,12.324 U4.48@37.373,12.324
  Top Layer w0.25: C33.1@44.296,19.562 44.296,19.758 C15.2@45.203,20.664 ; 49.511,15.944 ccw(c49.572,16.004) 49.572,15.919 v4@49.711,15.919
  Top Layer w0.3: U4.48@37.373,12.324 37.949,12.324 U4.49@40.701,15.075 ; U1.8@47.736,16.318 ccw(c48.701,17.283) 48.464,15.939 cw(c48.524,15.519) 48.524,15.944 49.511,15.944
  Top Layer w0.4: v1@37.143,11.405 37.143,11.872 37.204,11.932 U4.48@37.204,12.224
  Top Layer w0.625: v1@39.964,25.913 40.521,25.913 40.521,26.924 C37.1@40.503,26.942 ; C26.2@44.368,24.77 C26.2@44.458,24.68
  Top Layer w1.4: v1@19.127,26.654 cw(c20.977,26.654) 20.977,28.504 23.803,28.504 37.548,28.504 ; 38.077,28.504 37.548,28.504 ; 49.003,28.504 37.548,28.504
  Top Layer w1.5: v1@19.127,26.654 19.127,25.192 19.127,23.992 19.127,22.742 19.127,21.592 19.127,20.392 19.127,19.192 19.127,17.992 19.127,15.592 19.127,13.192 19.127,11.942 19.127,9.154 ccw(c20.977,9.154) 20.977,7.304 ; 20.982,7.3 20.977,7.304 ; 49.003,28.504 51.502,28.504 cw(c51.502,26.654) 53.352,26.654 ; 53.328,17.416 53.328,19.142 53.328,20.392 53.328,21.592 53.328,22.792 53.328,23.992 53.328,25.192 v1@53.328,26.448 ; v1@53.35,9.106 53.35,9.154 53.35,10.742 53.35,11.942 53.35,13.192 53.35,14.335 ; v1@53.352,9.154 cw(c51.502,9.154) 51.502,7.304 43.525,7.304 21.403,7.304 20.977,7.304
  MidLayer 1 w0.2: CN2.3@47.783,3.192 CN2.3@47.783,3.366
  Bottom Layer w0.5: C39.2@37.277,17.848 38.239,18.81 C14.2@38.769,18.81 ; 43.778,22.815 45.546,22.815 ; 43.833,24.991 45.546,23.279 45.546,22.815 ; 45.546,22.349 45.546,22.815 ; 46.546,22.349 46.081,22.815 45.546,22.815
  other v1: 5.603,4.702 8.24,4.722 52.559,4.855 15.894,4.98 20.928,4.962 18.374,5.036 31.517,5.132 10.854,5.195 44.259,5.384 26.235,5.432 23.422,5.509 28.665,5.501 36.757,5.639 52.607,5.628 34.36,5.698 8.269,5.727 5.646,5.782 41.745,5.802 15.894,5.856 20.982,5.98 40.155,6.015 10.84,6.086 13.783,6.114 52.617,6.478 18.471,6.484 21.665,7.185 26.915,7.191 23.117,7.206 24.353,7.206 25.558,7.206 28.316,7.206 29.688,7.221 35.433,7.241 31.92,7.247 33.037,7.254 34.382,7.279 36.939,7.291 37.926,7.291 39.002,7.317 41.321,7.313 42.326,7.313 5.655,7.344 43.38,7.335 45.328,7.339 48.548,7.326 44.335,7.364 16.09,7.414 51.95,7.493 50.582,7.522 19.958,7.574 17.672,7.817 11.586,7.881 52.916,8.022 13.671,8.326 50.982,8.552 44.035,8.921 51.961,8.926 53.277,8.923 19.153,8.955 21.332,8.996 43.132,9.024 17.176,9.213 44.805,9.264 51.141,9.408 43.035,9.646 59.458,9.648 60.458,9.648 61.458,9.648 51.896,9.738 19.063,9.904 53.328,9.967 58.962,9.997 59.962,9.997 60.962,9.997 11.727,10.059 9.175,10.402 14.249,10.514 32.895,10.661 58.754,10.691 62.943,10.749 53.29,10.882 36.51,10.903 32.036,10.94 33.564,11.038 35.094,11.038 58.404,11.186 62.594,11.244 16.402,11.302 21.177,11.322 36.927,11.32 19.115,11.377 23.969,11.384 29.615,11.517 58.754,11.691 62.943,11.749 11.622,11.828 52.025,11.851 6.007,11.894 9.017,11.895 53.303,11.951 22.666,12.19 58.404,12.186 19.093,12.349 59.649,12.442 60.649,12.442 61.649,12.442 62.649,12.442 47.575,12.625 58.754,12.691 53.341,12.866 15.141,12.896 29.882,12.889 20.96,12.935 38.471,12.962 39.371,12.962 40.271,12.962 41.171,12.962 42.071,12.962 42.971,12.962 58.404,13.186 17.505,13.281 49.28,13.299 47.598,13.354 12.27,13.386 19.072,13.386 46.827,13.424 50.063,13.508 6.376,13.563 29.882,13.575 58.754,13.691 9.211,13.704 53.303,13.819 38.471,13.862 39.371,13.862 40.271,13.862 41.171,13.862 42.071,13.862 42.971,13.862 49.594,14.067 47.159,14.09 46.341,14.106 58.404,14.186 32.283,14.299 32.873,14.299 31.674,14.461 38.471,14.762 39.371,14.762 40.271,14.762 41.171,14.762 42.071,14.762 42.971,14.762 22.325,15.199 17.067,15.259 13.881,15.382 21.146,15.571 19.05,15.59 38.471,15.662 39.371,15.662 40.271,15.662 41.171,15.662 42.071,15.662 42.971,15.662 5.949,15.68 11.22,16.012 38.471,16.562 39.371,16.562 40.271,16.562 41.171,16.562 42.071,16.562 42.971,16.562 15.754,16.888 19.052,16.944 9.766,16.975 39.371,17.462 40.271,17.462 41.171,17.462 42.071,17.462 42.971,17.462 6.79,17.483 12.883,17.57 58.754,17.881 53.016,17.933 58.404,18.376 15.194,18.638 19.082,18.64 50.396,18.704 48.736,18.734 53.664,18.851 58.754,18.881 5.932,18.971 9.521,19.024 11.92,19.041 48.297,19.234 49.516,19.244 59.683,19.354 60.683,19.354 61.683,19.354 62.683,19.354 58.404,19.376 36.905,19.627 50.245,19.671 48.736,19.734 52.971,19.845 58.754,19.881 36.39,19.906 62.978,20.048 15.159,20.197 48.297,20.234 19.122,20.267 49.529,20.299 58.404,20.376 62.628,20.552 33.743,20.629 48.736,20.734 50.308,20.801 47.509,20.817 58.754,20.881 53.619,21.005 62.978,21.048 48.297,21.234 35.2,21.253 44.397,21.254 49.583,21.331 45.117,21.346 58.404,21.376 39.348,21.559 33.47,21.67 45.851,21.659 19.081,21.704 46.736,21.734 47.736,21.734 48.736,21.734 59.165,21.768 60.165,21.768 61.165,21.768 62.165,21.768 50.426,21.789 45.221,21.974 39.983,21.982 59.66,22.117 60.66,22.117 61.66,22.117 46.236,22.173 47.236,22.173 48.236,22.173 53.031,22.165 39.219,22.385 49.601,22.426 50.45,22.888 53.694,22.933 19.153,23.043 29.892,23.14 47.935,23.144 32.936,23.166 38.902,23.21 49.819,23.577 31.297,23.686 28.526,23.83 36.921,23.935 19.141,24.123 53.137,24.152 48.32,24.424 50.499,24.445 43.833,24.741 49.189,24.815 37.717,24.825 53.589,25.237 19.114,25.501 35.252,25.648 38.54,25.714 48.863,25.836 39.964,25.932 48.124,26.271 53.152,26.336 19.136,26.462 36.068,26.472 39.283,26.51 23.778,26.663 49.79,26.825 48.863,26.923 22.372,27.17 33.557,27.167 36.772,27.167 34.697,27.211 51.864,27.256 26.567,27.285 53.297,27.379 40.63,28.009 41.911,28.009 37.751,28.044 47.234,28.03 48.472,28.03 43.258,28.052 45.887,28.052 44.562,28.074 52.322,28.094 19.785,28.123 23.155,28.534 28.67,28.541 30.389,28.534 32.6,28.541 34.207,28.532 35.386,28.541 25.179,28.559 26.634,28.577 21.351,28.582 6.177,28.959 11.703,28.946 14.429,28.938 17.171,28.946 8.919,28.963 39.046,29.571 47.842,29.66 42.687,29.694 43.936,29.687 40.148,29.707 41.372,29.7 45.257,29.713 46.585,29.707 23.756,30.2
  other v2: 2.269,0.408 3.145,0.393 4.245,0.393 5.345,0.393 6.445,0.393 7.545,0.393 8.645,0.393 9.745,0.393 10.845,0.393 11.945,0.393 13.045,0.393 14.145,0.393 15.245,0.393 16.345,0.393 17.445,0.393 18.545,0.393 19.645,0.393 20.745,0.393 21.845,0.393 22.945,0.393 24.045,0.393 25.145,0.393 26.245,0.393 27.345,0.393 28.445,0.393 29.545,0.393 30.645,0.393 31.745,0.393 32.845,0.393 33.945,0.393 35.045,0.393 36.145,0.393 37.245,0.393 38.345,0.393 39.445,0.393 40.545,0.393 41.645,0.393 42.745,0.393 43.845,0.393 44.945,0.393 46.045,0.393 47.145,0.393 48.245,0.393 49.345,0.393 50.445,0.393 51.545,0.393 52.645,0.393 53.745,0.393 54.845,0.393 55.945,0.393 57.045,0.393 58.145,0.393 59.245,0.393 60.345,0.393 61.445,0.393 62.545,0.393 2.595,1.345 3.695,1.345 4.795,1.345 5.895,1.345 6.995,1.345 8.095,1.345 9.195,1.345 10.295,1.345 11.395,1.345 12.495,1.345 13.595,1.345 14.7,1.35 15.795,1.345 16.895,1.345 17.995,1.345 19.095,1.345 20.195,1.345 21.295,1.345 22.395,1.345 23.495,1.345 24.595,1.345 25.695,1.345 26.795,1.345 27.895,1.345 28.995,1.345 30.095,1.345 31.195,1.345 32.295,1.345 33.395,1.345 34.495,1.345 35.595,1.345 36.695,1.345 37.795,1.345 38.895,1.345 39.995,1.345 41.095,1.345 42.195,1.345 43.295,1.345 44.395,1.345 45.495,1.345 46.595,1.345 47.695,1.345 48.795,1.345 49.895,1.345 50.995,1.345 52.095,1.345 53.195,1.345 54.295,1.345 55.395,1.345 56.495,1.345 57.595,1.345 58.695,1.345 59.795,1.345 60.895,1.345 61.995,1.345 63.095,1.345 3.146,1.945 62.179,2.096 2.252,2.202 63.095,2.445 3.205,2.752 62.142,2.995 2.252,3.302 63.095,3.545 3.205,3.852 62.142,4.095 2.252,4.402 63.095,4.645 3.205,4.952 62.142,5.195 2.252,5.502 63.095,5.745 3.205,6.052 62.142,6.295 2.252,6.602 63.095,6.845 3.205,7.152 62.142,7.395 2.252,7.702 63.095,7.945 3.205,8.252 62.142,8.495 2.252,8.802 63.095,9.045 3.205,9.352 62.142,9.595 2.252,9.902 63.095,10.145 3.205,10.452 62.142,10.695 2.252,11.002 3.205,11.552 2.252,12.102 3.205,12.652 2.252,13.202 3.205,13.752 2.252,14.302 3.205,14.852 2.252,15.402 3.205,15.952 2.252,16.502 3.205,17.052 2.252,17.602 3.205,18.152 2.252,18.702 3.205,19.252 2.252,19.802 3.205,20.352 2.252,20.902 3.205,21.452 63.081,21.931 2.252,22.002 62.128,22.481 3.205,22.552 63.081,23.031 2.252,23.102 62.128,23.581 3.205,23.652 63.081,24.131 2.252,24.202 62.128,24.681 3.205,24.752 63.081,25.231 2.252,25.302 62.128,25.781 3.205,25.852 63.081,26.331 2.252,26.402 62.128,26.881 3.205,26.952 63.081,27.431 2.252,27.502 62.128,27.981 3.205,28.052 63.081,28.531 2.252,28.602 62.128,29.081 3.205,29.152 63.081,29.631 2.252,29.702 62.128,30.181 3.205,30.252 63.081,30.731 2.252,30.802 62.128,31.281 3.205,31.352 63.081,31.831 2.252,31.902 61.832,32.009 3.205,32.452 3.964,32.761 5.064,32.761 6.164,32.761 7.264,32.761 8.364,32.761 9.464,32.761 10.564,32.761 11.664,32.761 12.764,32.761 13.864,32.761 14.964,32.761 16.064,32.761 17.164,32.761 18.264,32.761 19.364,32.761 20.464,32.761 21.564,32.761 22.664,32.761 23.764,32.761 24.864,32.761 25.964,32.761 27.064,32.761 28.164,32.761 29.264,32.761 30.364,32.761 31.464,32.761 32.564,32.761 33.664,32.761 34.764,32.761 35.864,32.761 36.964,32.761 39.164,32.761 40.264,32.761 41.364,32.761 42.464,32.761 43.564,32.761 44.664,32.761 45.764,32.761 46.864,32.761 47.964,32.761 49.064,32.761 50.164,32.761 51.264,32.761 52.364,32.761 53.464,32.761 54.564,32.761 55.664,32.761 56.764,32.761 57.864,32.761 58.964,32.761 60.064,32.761 61.164,32.761 62.264,32.761 63.081,32.931 2.252,33.002 2.314,33.714 3.414,33.714 4.514,33.714 5.614,33.714 6.714,33.714 7.814,33.714 8.914,33.714 10.014,33.714 11.114,33.714 12.214,33.714 13.314,33.714 14.414,33.714 15.514,33.714 16.614,33.714 17.714,33.714 18.814,33.714 19.914,33.714 21.014,33.714 22.114,33.714 23.214,33.714 24.314,33.714 25.414,33.714 26.514,33.714 27.614,33.714 28.714,33.714 29.814,33.714 30.914,33.714 32.014,33.714 33.114,33.714 34.214,33.714 35.314,33.714 36.414,33.714 37.514,33.714 38.614,33.714 39.714,33.714 40.814,33.714 41.914,33.714 43.014,33.714 44.114,33.714 45.214,33.714 46.314,33.714 47.414,33.714 48.514,33.714 49.614,33.714 50.714,33.714 51.814,33.714 52.914,33.714 54.014,33.714 55.114,33.714 56.214,33.714 57.314,33.714 58.414,33.714 59.514,33.714 60.614,33.714 61.714,33.714 62.814,33.714
  other v3: 55.963,2.152 49.202,2.224 46.339,2.261 55.103,2.672 56.263,2.672 57.423,2.672 58.583,2.672 59.743,2.672 60.903,2.672 18.563,3.832 31.323,3.832 54.523,3.832 55.683,3.832 56.843,3.832 58.003,3.832 59.163,3.832 60.323,3.832 49.081,4.318 13.343,4.992 53.943,4.992 55.103,4.992 56.263,4.992 57.423,4.992 58.583,4.992 59.743,4.992 60.903,4.992 48.723,6.152 53.363,6.152 54.523,6.152 55.683,6.152 56.843,6.152 58.003,6.152 59.163,6.152 60.323,6.152 54.006,6.822 7.703,7.232 9.312,7.232 4.063,7.312 6.383,7.312 12.183,7.312 16.823,7.312 52.783,7.312 56.263,7.312 57.423,7.312 58.583,7.312 59.743,7.312 60.903,7.312 54.62,7.743 5.803,8.472 8.123,8.472 16.243,8.472 17.403,8.472 20.883,8.472 55.683,8.472 56.843,8.472 58.003,8.472 59.163,8.472 60.323,8.472 54.901,8.815 4.063,9.632 5.223,9.632 6.383,9.632 14.503,9.632 17.983,9.632 53.943,9.632 56.263,9.632 54.921,9.923 58.013,9.924 11.603,10.792 15.083,10.792 55.683,10.792 57.394,10.843 54.921,11.031 17.556,11.484 4.063,11.952 5.223,11.952 14.503,11.952 15.663,11.952 16.823,11.952 20.303,11.952 21.463,11.952 57.365,11.951 54.921,12.139 25.483,12.312 55.963,12.312 17.556,12.592 57.719,13.001 8.123,13.112 11.603,13.112 16.243,13.112 22.043,13.112 29.003,13.112 52.203,13.112 55.683,13.112 56.843,13.112 54.921,13.247 63.177,13.367 62.07,13.421 60.963,13.459 59.855,13.487 56.604,14.036 55.514,14.237 4.063,14.272 12.183,14.272 13.343,14.272 14.503,14.272 28.423,14.272 52.783,14.272 20.699,15.032 10.443,15.432 12.763,15.432 15.083,15.432 16.243,15.432 17.556,15.916 20.699,16.14 4.063,16.592 6.383,16.592 12.183,16.592 14.503,16.592 16.823,16.592 26.103,16.592 29.583,16.592 34.223,16.592 17.556,17.024 33.103,17.392 54.899,17.555 5.803,17.752 10.443,17.752 27.843,17.752 29.003,17.752 55.683,17.752 56.843,17.752 59.833,18.299 60.941,18.32 20.699,18.356 62.048,18.35 63.155,18.397 57.65,18.625 54.899,18.663 4.063,18.912 7.543,18.912 8.703,18.912 23.783,18.912 27.263,18.912 28.423,18.912 29.583,18.912 52.783,18.912 56.263,18.912 57.39,19.702 54.899,19.771 6.963,20.072 9.283,20.072 10.443,20.072 12.763,20.072 13.923,20.072 16.243,20.072 20.883,20.072 25.523,20.072 26.683,20.072 27.843,20.072 29.003,20.072 30.163,20.072 55.683,20.072 17.556,20.348 57.429,20.809 54.899,20.879 9.863,21.232 11.023,21.232 21.463,21.232 24.943,21.232 26.103,21.232 27.263,21.232 28.423,21.232 29.583,21.232 30.743,21.232 52.783,21.232 56.263,21.232 20.699,21.68 17.548,21.711 54.899,21.987 6.963,22.392 9.283,22.392 10.443,22.392 11.603,22.392 23.203,22.392 24.363,22.392 25.523,22.392 26.683,22.392 27.843,22.392 29.003,22.392 33.643,22.392 56.843,22.392 58.003,22.392 55.963,22.472 54.899,23.095 9.863,23.552 11.023,23.552 13.343,23.552 22.623,23.552 23.783,23.552 24.943,23.552 26.103,23.552 27.263,23.552 37.703,23.552 52.783,23.552 56.263,23.552 57.423,23.552 58.583,23.552 59.743,23.552 60.903,23.552 54.899,24.203 49.844,24.545 6.963,24.712 12.763,24.712 15.083,24.712 16.243,24.712 55.683,24.712 56.843,24.712 58.003,24.712 59.163,24.712 60.323,24.712 54.899,25.311 4.063,25.872 6.383,25.872 7.543,25.872 11.023,25.872 12.183,25.872 14.503,25.872 17.556,25.888 53.943,25.872 56.263,25.872 57.423,25.872 58.583,25.872 59.743,25.872 60.903,25.872 54.9,26.419 17.599,26.995 25.815,26.983 5.803,27.032 6.963,27.032 9.283,27.032 11.603,27.032 13.923,27.032 15.083,27.032 23.203,27.032 55.683,27.032 56.843,27.032 58.003,27.032 59.163,27.032 60.323,27.032 54.807,27.523 6.383,28.192 8.703,28.192 11.023,28.192 14.503,28.192 16.823,28.192 29.583,28.192 31.903,28.192 55.103,28.192 56.263,28.192 57.423,28.192 58.583,28.192 59.743,28.192 60.903,28.192 54.36,28.537 34.803,29.352 53.604,29.347 54.523,29.352 55.683,29.352 56.843,29.352 58.003,29.352 59.163,29.352 60.323,29.352 52.633,29.88 33.767,30.025 49.278,30.076 51.542,30.077 26.103,30.512 38.863,30.512 55.103,30.512 56.263,30.512 57.423,30.512 58.583,30.512 59.743,30.512 60.903,30.512 54.523,31.672 55.683,31.672 56.843,31.672 58.003,31.672 59.163,31.672 60.323,31.672
  other v4: 57.195,13.718 57.827,13.775 47.971,13.847 48.435,13.847 48.897,13.847 54.47,14.236 48.921,14.306 47.959,14.346 49.365,14.589 50.165,14.589 45.891,14.733 46.566,14.733 47.241,14.733 56.322,14.797 54.296,14.828 51.035,14.881 55.629,14.943 57.232,14.947 48.981,14.978 49.781,14.978 50.571,14.98 52.582,14.977 53.382,14.977 54.982,14.977 58.059,14.972 47.8,15.218 56.836,15.297 52.199,15.366 52.999,15.366 53.799,15.366 55.364,15.367 56.167,15.348 57.675,15.361 47.8,15.878 49.743,16.063 48.887,16.321 49.36,16.452 50.16,16.452 52.199,16.471 52.999,16.471 53.799,16.471 54.599,16.471 55.399,16.471 56.999,16.471 57.799,16.471 47.8,16.736 52.582,16.86 53.382,16.86 54.182,16.86 54.982,16.86 55.782,16.86 56.582,16.86 57.382,16.86 58.182,16.86 58.528,17.346 50.853,17.401 58.046,17.459 47.182,17.572 47.728,17.739 48.528,17.739 49.328,17.739 50.128,17.739 50.64,17.929 48.111,18.128 48.911,18.128 49.711,18.128 46.25,18.21 46.972,18.2 47.605,18.444 48.13,18.698 46.591,18.717 43.973,18.787 47.362,19.048 44.258,19.147 47.562,19.841
NetC6_1: C6.1 C7.1 L1.2 U4.41 | length 8.4
  Top Layer w0.254: v1(32.983,15.832) v1(36.843,15.832) v1@36.883,15.832 ; v1@36.883,15.824 U4.41@37.302,15.824
  Bottom Layer w0.254: 32.087,15.742 32.177,15.832 v1(32.983,15.832) ; v1(36.843,15.832) 36.885,15.874 C7.1@36.885,16.212
  Bottom Layer w0.4: L1.2@30.789,15.279 31.625,15.279 32.087,15.742 C6.1@32.087,16.977
  Bottom Layer w0.5: L1.2@30.789,15.279 L1.2@30.842,15.331
NetC8_1: C8.1 U4.39 X1.2 | length 8.3
  Top Layer w0.254: C8.1@32.017,22.152 31.998,22.133 X1.2@31.998,20.904 32.371,20.531 32.7,20.531 36.377,16.854 U4.39@37.404,16.854
NetC9_1: C9.1 U4.40 X1.1 | length 7.9
  Top Layer w0.254: X1.1@31.998,19.404 32.044,19.358 C9.1@32.044,18.172 ; X1.1@32.044,19.424 32.202,19.266 32.856,19.266 35.768,16.354 U4.40@37.404,16.354
NetC12_1: C12.1 R212.1 U2.1 U4.18 | length 15.3
  Top Layer w0.15: U4.18@44.099,14.824 44.669,14.824 45.368,14.124 45.368,13.545 47.358,11.555 47.358,9.037 47.624,8.772 v1(47.903,8.772)
  Top Layer w0.2: R212.1@45.394,5.371 46.119,5.371 v1@46.13,5.382 ; v1(47.903,8.772) 48.611,8.772 U2.1@48.691,8.692 ; C12.1@48.691,9.379 C12.1@48.803,9.492
  Top Layer w0.4: U2.1@48.691,8.692 C12.1@48.691,9.379
  Bottom Layer w0.15: v1@46.07,5.425 47.133,5.425 47.903,6.195 v1(47.903,8.772)
  other v1: 46.117,5.403
NetC13_2: C13.2 C16.2 R2.1 U3.4 | length 3.1
  Top Layer w0.2: C13.2@51.167,14.2 C16.2@51.167,13.515 51.502,13.18 R2.1@51.502,12.72 ; C13.2@51.167,14.2 51.167,14.211 51.611,14.655 U3.4@51.611,15.519
NetC15_1: C15.1 C18.2 L3.1 U4.24 | length 3.6
  Top Layer w0.2: U4.24@44.099,17.824 44.233,17.824 44.652,18.242 44.91,18.242 45.022,18.354 L3.1@45.022,18.521 ; L3.1@45.11,18.408 45.11,18.521 45.168,18.579 45.168,19.431 C15.1@45.203,19.466 ; C15.1@45.219,19.466 C15.1@45.468,19.466
  Top Layer w0.4: C15.1@45.468,19.453 46.167,19.453 C18.2@46.406,19.453
NetC19_1: C19.1 U3.1 | length 1.9
  Top Layer w0.25: C19.1@49.611,17.158 cw(c49.611,15.323) 50.909,16.621 U3.1@51.211,16.319
NetC19_2: C19.2 U1.6 | length 0.6
  Top Layer w0.25: U1.6@48.426,17.158 C19.2@49.011,17.158
NetC23_2: C23.2 C41.1 R3.1 U3.6 | length 2.3
  Top Layer w0.2: U3.6@51.611,16.319 51.611,16.605 51.792,16.786 C23.2@51.792,17.196 C41.1@51.792,17.882 R3.1@51.792,18.566
NetC25_1: C25.1 C50.2 U3.5 | length 3.4
  Top Layer w0.25: U3.5@51.611,15.919 54.362,15.919 C25.1@55.036,15.919
NetC25_2: C25.2 C29.2 L7.1 | length 1.3
  Top Layer w0.25: C25.2@55.649,15.898 55.636,15.91 C25.2@55.636,15.919 56.848,15.919 L7.1@56.854,15.925 ; L7.1@56.862,15.908 L7.1@56.873,15.919
NetC26_1: C26.1 C36.2 X2.1 | length 2.7
  Top Layer w0.2: X2.1@42.998,25.82 X2.1@43.188,25.82 ; C26.1@44.4,25.82 C26.1@44.422,25.842
  Top Layer w0.3: X2.1@43.188,25.82 C26.1@44.4,25.82 ; C26.1@44.422,25.842 44.551,25.714 44.945,25.714 44.98,25.679 45.441,25.679 C36.2@45.603,25.842
NetC27_2: C27.2 U1.4 U3.3 | length 3.4
  Top Layer w0.25: C27.2@48.418,14.861 C27.2@48.428,14.861 C27.2@48.45,14.861 ; C27.2@48.426,14.898 48.426,15.478 51.114,15.478 ccw(c51.114,15.616) U3.3@51.211,15.519
NetC28_2: C28.2 J3.1 L7.2 | length 3.5
  Top Layer w0.25: L7.2@57.584,15.919 C28.2@58.084,15.919 ; C28.2@58.206,15.919 J3.1@61.193,15.919
NetC31_1: C31.1 SB15.2 X2.3 | length 2.7
  Top Layer w0.254: C31.1@40.521,24.715 C31.1@40.576,24.77
  Top Layer w0.3: C31.1@40.576,24.77 X2.3@41.838,24.77
  Top Layer w0.4: SB15.2@41.803,23.442 41.803,24.735 X2.3@41.838,24.77
NetC36_1: C36.1 R100.2 | length 1.1
  Top Layer w0.3: R100.2@46.803,24.692 C36.1@46.803,25.84
NetC37_2: C37.2 L9.1 X2.2 | length 5.3
  Top Layer w0.4: C37.2@41.701,26.942 L9.1@45.803,26.942
  Top Layer w0.625: C37.2@41.701,26.942 41.701,25.957 X2.2@41.838,25.82
NetC200_1: C200.1 U1.1 | length 0.6
  Top Layer w0.25: C200.1@46.462,16.818 U1.1@47.046,16.818
NetC200_2: C200.2 L3.2 U4.23 | length 2
  Top Layer w0.25: U4.23@44.099,17.324 44.101,17.325 45.018,17.325 L3.2@45.031,17.338 ; L3.2@45.11,17.348 45.368,17.348 45.913,16.804 C200.2@45.966,16.804
NetC201_1: C201.1 CN1.10 R201.2 | length 3.7
  Top Layer w0.2: CN1.10@30.01,31.127 30.227,30.91 31.018,30.91 32.193,29.736 32.193,29.571 32.193,29.535 R201.2@32.208,29.521 32.84,29.521 C201.1@32.853,29.508
  Top Layer w0.25: R201.2@32.193,29.571 R201.2@32.223,29.571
